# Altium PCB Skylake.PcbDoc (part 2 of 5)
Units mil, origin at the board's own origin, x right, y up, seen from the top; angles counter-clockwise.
Board outline 4000 x 4000 mil, 8 copper layers (TOP LAYER, GND1#2, SIG1#3, SIG2#4, GND2#5, SIG3#6, GND3#7, BOTTOM LAYER), stack 132.6 mil thick; 343 components, 142 nets, 972 pads, 752 vias.
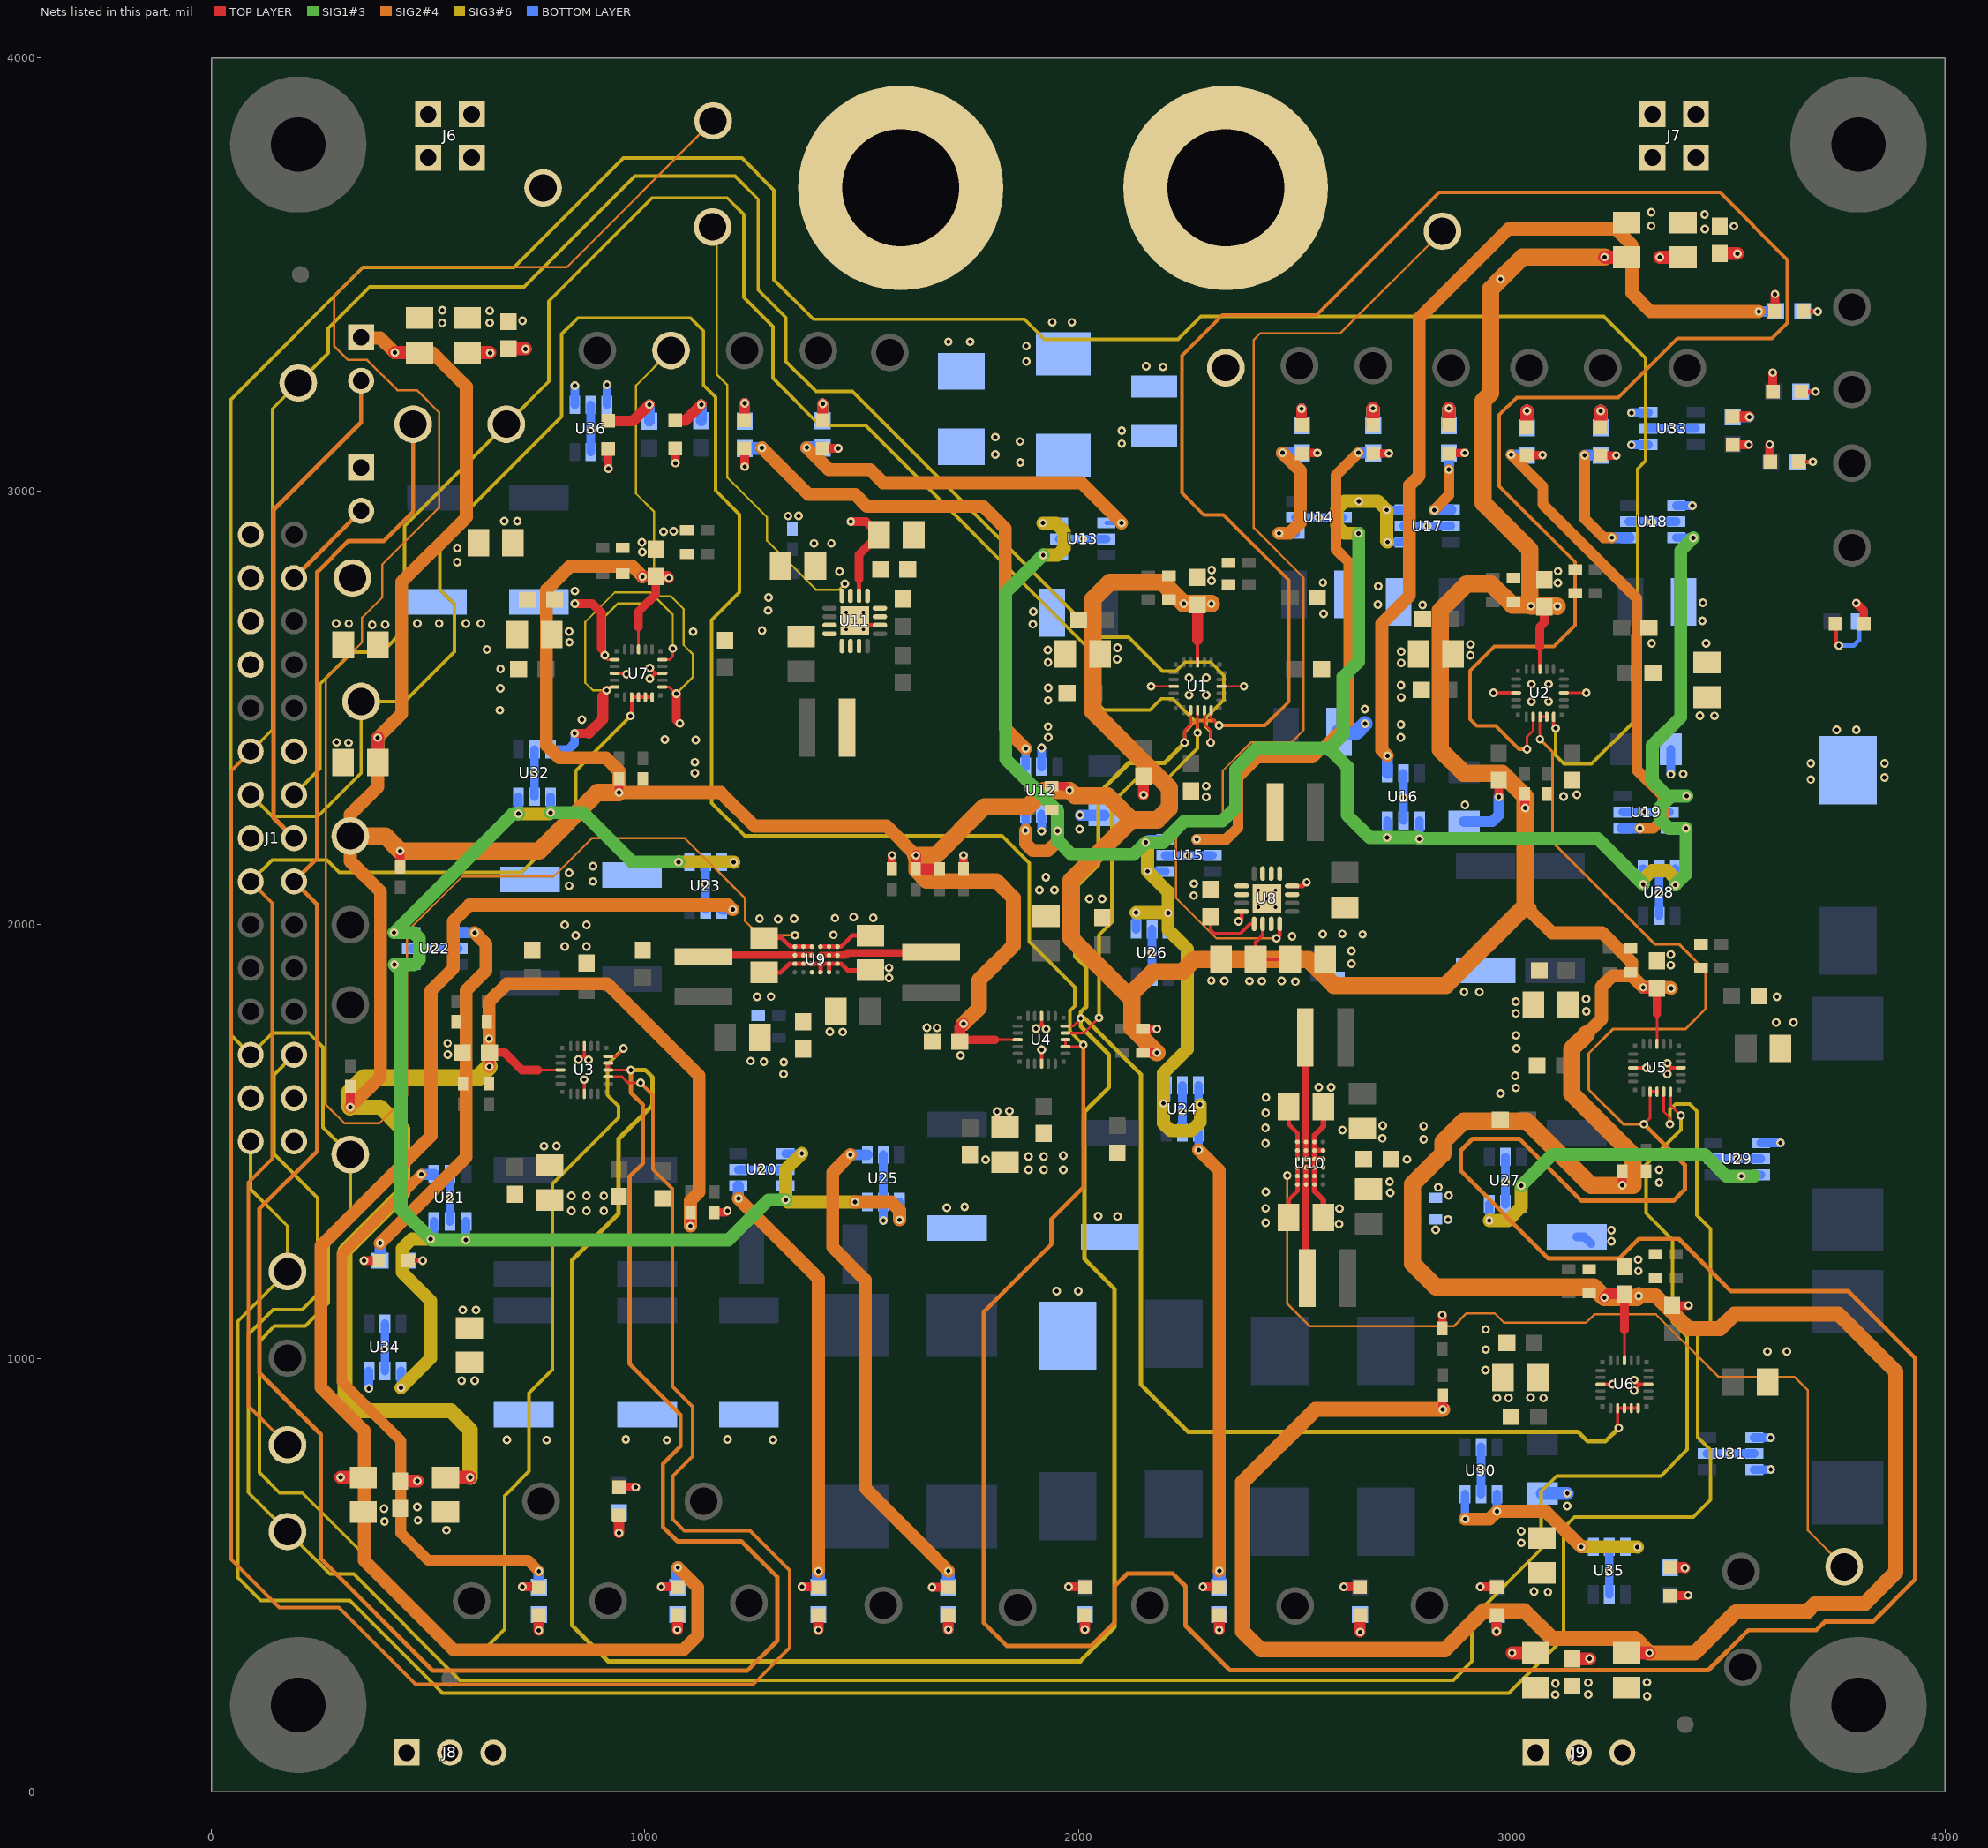
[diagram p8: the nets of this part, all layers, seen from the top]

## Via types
v1: diameter 20, hole 10, TOP LAYER to BOTTOM LAYER, 742 vias
v2: diameter 19.68, hole 7.87, TOP LAYER to BOTTOM LAYER, 10 vias

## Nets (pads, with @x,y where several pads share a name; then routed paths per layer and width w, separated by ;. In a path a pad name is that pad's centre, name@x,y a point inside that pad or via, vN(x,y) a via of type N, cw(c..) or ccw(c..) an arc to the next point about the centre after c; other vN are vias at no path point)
+3.3V_USB: +3.3V_USB.1 C15.1 C16.1 C17.1 C18.1 C20.1 C26.1 C36.1 C52.1 C62.1 C78.1 C88.1 C102.1 J14.1 R1.2 R2.2 R29.2 R30.2 R31.2 R39.2 R40.2 R41.2 R50.2 R51.2 R52.2 R62.2 R63.2 R64.2 R75.2 R76.2 R77.2 R87.2 R88.2 R89.2 R99.2 R100.2 R101.2 U1.18 U2.18 U3.18 U4.18 U5.18 U6.18 U7.18 | length 21363.5
  TOP LAYER w6: 752.95,1665 U3.18@804.88,1665 ; U7.18@985,2635.12 985,2687.05 ; 1807.95,1734.68 U4.18@1859.88,1734.68 ; U6.18@3260,995.12 3260,1065 ; U5.18@3335,1725.12 3335,1795
  TOP LAYER w8: 2274.42,2657.63 2275,2657.05 U1.18@2275,2605.12 ; 3064.42,2642.63 3065,2642.05 U2.18@3065,2590.12
  TOP LAYER w20: v1(319.77,1579.52) 320,1579.75 R2.2@320,1626.38 ; R1.2@435,2133.62 435,2170.13 v1(435.1,2170.23) ; v1(640.46,1672.95) 641.5,1673.99 C52.1@641.5,1705 676.16,1705 716.16,1665 752.95,1665 ; v1(940,2305) R99.2@940,2336.38 ; 985,2687.05 985,2722.17 1025,2762.17 C102.1@1025,2803.5 ; v1(1105,1305) R50.2@1105,1336.38 ; C62.1@1726.5,1730 1731.18,1734.68 1807.95,1734.68 ; R29.2@1938.62,2320 1969.73,2320 v1(1979.78,2309.95) ; R62.2@2148.62,1705 2181.03,1705 v1(2181.07,1704.96) ; v1(2840.86,881.68) v1(2840.86,881.68) R87.2@2840.9,913.93 ; R39.2@3030,2301.38 3030,2270.7 v1(3031.03,2269.67) ; 3064.42,2642.63 3064.42,2686.35 3075,2696.93 C36.1@3075,2733.5 ; v1(3255.01,1398.78) R75.2@3255,1431.38 ; 3260,1065 C88.1@3260,1148.5 ; 3335,1795 C78.1@3335,1853.5
  TOP LAYER w25: v1(994.44,2803.06) 994.88,2803.5 C102.1@1025,2803.5 1051.5,2803.5 v1(1055,2800) ; v1(1625,2160) R64.2@1625,2128.62 R63.2@1680,2128.62 ; C62.1@1726.5,1730 1726.5,1763.5 v1(1735,1772) ; 2274.42,2657.63 2275,2658.21 C26.1@2275,2738.5 ; v1(3213.7,1139.66) 3222.54,1148.5 C88.1@3260,1148.5 ; v1@3305.33,1853.5 C78.1@3335,1853.5
  TOP LAYER w30: v1(383.42,2431.72) 383.51,2431.63 C20.1@383.51,2373.96 ; v1(422.89,3319.79) 423.1,3320 C18.1@480,3320 ; C15.1@540,725 v1@596.52,725 ; v1(3214.16,3540.36) 3214.52,3540 C17.1@3265,3540 ; C16.1@3265,320 v1(3317.67,320)
  SIG2#4 w30: v1(319.77,1579.52) 389.5,1649.25 389.5,2076.81 320,2146.31 +3.3V_USB.1@320,2205 320,2254.74 383.42,2318.16 v1(383.42,2431.72) 438.38,2486.68 438.38,2790.85 587.82,2940.29 587.82,3241.5 509.53,3319.79 v1(422.89,3319.79) 389.17,3353.51 346.49,3353.51 J14.1@345,3355 ; v1(640.46,1672.95) 640.23,1673.18 v1(640.23,1737.31) 640.23,1822.7 681.6,1864.07 912.97,1864.07 1124.93,1652.11 1124.93,1383.56 1105,1363.63 v1(1105,1305) ; v1(994.44,2803.06) 969.89,2827.61 827.99,2827.61 772.66,2772.28 772.66,2414.18 801.84,2385 910,2385 940,2355 v1(940,2305) 1175,2305 1252,2228 1557,2228 v1(1625,2160) ; 3037,2037 3092.48,1981.52 3208.52,1981.52 3276.64,1913.4 3276.64,1882.19 ; 3172.33,1747.48 3207.1,1782.25 3207.1,1857.21 3232.08,1882.19 3276.64,1882.19 ; v1(3368.07,1853.31) 3365.84,1855.54 v1(3303.29,1855.54) 3276.64,1882.19
  SIG2#4 w35: v1(1625,2160) 1625,2125 1649,2101 1811,2101 1850,2062 1850,1952 1771,1873 1771,1808 v1(1735,1772) ; v1(2840.86,881.68) 2546.84,881.68 2379.12,713.96 2379.12,369.56 2421.11,327.57 2845.57,327.57 2935.04,417.04 3029.13,417.04 3092.37,353.8 3283.87,353.8 v1(3317.67,320) 3422.18,320 3517.07,414.89 3680.85,414.89 3698.86,432.9 3813.27,432.9 3885.87,505.5 3885.87,969.64 3753.62,1101.89 3514.04,1101.89 3480.63,1068.48 3407.52,1068.48 3332.24,1143.76 v1(3292.99,1143.76)
  SIG2#4 w40: +3.3V_USB.1@320,2205 400.33,2205 v1(435.1,2170.23) 755.75,2170.23 890.52,2305 v1(940,2305) ; v1(1625,2160) 1671.12,2160 1783.35,2272.23 1883.41,2272.23 1921.13,2309.95 v1(1979.78,2309.95) 1991.91,2297.82 2067.18,2297.82 2123,2242 ; 2123.68,1827.89 1983.5,1968.07 1983.5,2102.5 2123,2242 ; v1(2181.07,1704.96) 2123.68,1762.35 2123.68,1842.71 2171.97,1891 2238.82,1891 2267.82,1920 2530,1920 2590,1860 2848.06,1860 3031.03,2042.97 ; v1(2306.73,2740.48) 2306.43,2740.78 v1(2243.04,2740.78) 2194.13,2789.69 2194.13,2790.33 2072.82,2790.33 2033.29,2750.8 2033.29,2492.55 2209.85,2315.99 2209.85,2269.6 2182.25,2242 2123,2242 ; 3037,2037 3031.03,2042.97 ; v1(3105.04,2734.48) 3104.18,2735.34 v1(3044.36,2735.34) v1@3041.85,2737.85 ; 3172.33,1747.48 3138.16,1713.31 3138.16,1610.43 3280.01,1468.58 3280.01,1398.78 3183.04,1398.78 3034.24,1547.58 2889.5,1547.58 2840.81,1498.89 2840.81,1471.53 2770.66,1401.38 2770.66,1218.62 2824.65,1164.63 3188.73,1164.63 v1(3213.7,1139.66) 3288.89,1139.66 v1(3292.99,1143.76) ; v1(3214.16,3540.36) 3024.64,3540.36 v1(2973.93,3489.65) 2951.23,3466.95 2951.23,3226.28 2933.93,3208.98 2933.93,2972.97 3041.85,2865.05 v1@3041.85,2737.85 ; 3031.03,2042.97 v1(3031.03,2269.67) 3031.03,2295.82 2977.19,2349.66 2889.21,2349.66 2834.69,2404.18 2834.69,2724.96 2895.68,2785.95 2953.01,2785.95 3001.11,2737.85 v1@3041.85,2737.85
  SIG3#6 w35: v1(319.77,1579.52) 389.21,1579.52 440.83,1527.9 440.83,1380.83 307.71,1247.71 307.71,916.95 345.69,878.97 552.27,878.97 596.55,834.69 v1(596.55,724.97)
  SIG3#6 w40: v1(319.77,1579.52) 319.77,1615.17 351.86,1647.26 614.77,1647.26 v1(640.46,1672.95)
  other v1: 1728.15,1698.65
+5V_USB: +5V_USB.1 C7.1 C8.1 C9.1 C10.1 C11.1 C12.1 C13.1 C14.1 C19.1 J15.1 U12.4 U12.6 U13.4 U13.6 U14.4 U14.6 U15.4 U15.6 U16.4 U16.6 U17.4 U17.6 U18.4 U18.6 U19.4 U19.6 U20.4 U20.6 U21.4 U21.6 U22.4 U22.6 U23.4 U23.6 U24.4 U24.6 U25.4 U25.6 U26.4 U26.6 U27.4 U27.6 U28.4 U28.6 U29.4 U29.6 U30.4 U30.6 U31.4 U31.6 U32.4 U32.6 U33.4 U33.6 U34.4 U34.6 U35.4 U35.6 U36.4 U36.6 | length 12583.7
  TOP LAYER w30: v1(297.7,725) C7.1@350,725 ; C8.1@435,716.5 474.7,716.5 v1(474.89,716.69) ; C13.1@590,3320 641.91,3320 v1(642.4,3319.51) ; C14.1@685,3328.5 724.47,3328.5 v1(724.55,3328.58) ; v1(3000.8,319.71) 3001.09,320 C9.1@3055,320 ; C10.1@3140,306.5 3179.82,306.5 v1(3179.86,306.46) ; v1@3341.56,3540 C11.1@3395,3540 ; C12.1@3480,3548.5 3520.65,3548.5 v1(3520.71,3548.44)
  SIG1#3 w30: v1(707.86,2256.06) 695.07,2256.06 v1(420.88,1981.87) 465.57,1981.87 479.11,1968.33 479.11,1919.49 467.68,1908.06 v1(421.55,1908.06) 437.09,1892.52 437.09,1343.59 v1(505.67,1275) 507.59,1273.09 v1(587.01,1273.09) 1192.54,1273.09 1284.67,1365.22 v1(1324.67,1365.22) ; v1(782.05,2258.72) 856.6,2258.72 970.63,2144.69 v1(1077.27,2144.69) ; v1(1918.82,2852.96) 1832.29,2766.43 1832.29,2381.75 1951.97,2262.07 v1(1951.97,2216.55) 1951.97,2194.39 1984.26,2162.1 2127.48,2162.1 v1(2155.08,2189.7) 2195.2,2189.7 2244.93,2239.43 2332.24,2239.43 2362.91,2270.1 2362.91,2358.79 2410.85,2406.73 2578.26,2406.73 ; v1(2646.57,2903.1) 2646.57,2607.5 2610.77,2571.7 2610.77,2439.24 2578.26,2406.73 ; v1(3021.76,1397.89) 3093.39,1469.52 3445.54,1469.52 3495.06,1420 v1(3530,1420) 3559.12,1420 3559.44,1420.32 ; v1(3303.26,2093.38) 3198.1,2198.54 v1(2786.87,2198.54) 2784.14,2201.27 v1(2712.5,2201.27) 2672.38,2201.27 2620.52,2253.13 2620.52,2364.47 2578.26,2406.73 ; 3368.52,2297.1 v1(3403.52,2297.1) ; v1(3376.92,2091.82) 3402.15,2117.05 v1(3402.15,2222.89) 3362.7,2222.89 3342.25,2243.34 3342.25,2270.83 3363.53,2292.11 3324.17,2331.48 3324.17,2413.43 3389.9,2479.16 3389.9,2863.73 v1(3418.84,2892.67)
  SIG2#4 w30: v1(1484.92,1360.6) 1567.89,1360.6 1587.25,1341.24 v1(1587.25,1319.18) ; v1(1878.11,2217.63) 1878.11,2187.56 1894.64,2171.03 1930.13,2171.03 1951.97,2192.87 v1(1951.97,2216.55) ; v1(2892.44,629.06) 2948.3,629.06 v1(2965.92,646.68) 3078.39,646.68 v1(3160.31,564.76)
  SIG3#6 w30: v1(436.88,931.65) 505.06,999.83 505.06,1132.56 439.84,1197.78 439.84,1252.58 462.26,1275 v1(505.67,1275) ; v1(707.86,2256.06) 779.39,2256.06 v1(782.05,2258.72) ; v1(1077.27,2144.69) 1204.51,2144.69 v1(1205.06,2144.14) ; v1(1362.03,1472.3) 1324.67,1434.94 v1(1324.67,1365.22) 1329.29,1360.6 v1(1484.92,1360.6) ; v1(1917.91,2926.79) 1947.8,2926.79 1967.12,2907.47 1967.12,2868.08 1952,2852.96 v1(1918.82,2852.96) ; v1(2133.06,2028.37) 2205.75,2028.37 v1(2207.01,2027.11) ; v1(2155.08,2189.7) 2159.62,2185.16 v1(2159.62,2123.34) 2207.01,2075.95 v1(2207.01,2027.11) ; v1(2281,1585) 2281,1544.66 2261.02,1524.68 2212.98,1524.68 2196,1541.66 v1(2196,1588) 2196,1657.55 2251.28,1712.83 2251.28,1944.24 2207.01,1988.51 v1(2207.01,2027.11) ; v1(2646.57,2903.1) 2613.62,2903.1 2596.25,2920.47 2596.25,2959.52 2613.8,2977.07 v1(2647.07,2977.07) 2691.17,2977.07 v1(2711.12,2957.12) 2711.12,2885.4 v1(2713.56,2882.96) ; v1(2948.08,1317.64) 2991.12,1317.64 3021.76,1348.28 v1(3021.76,1397.89) ; v1(3160.31,564.76) 3289.45,564.76 v1(3289.95,564.26) ; v1(3303.26,2093.38) 3303.26,2105.06 3323.35,2125.15 3359.11,2125.15 3376.92,2107.34 v1(3376.92,2091.82)
  BOTTOM LAYER w20: v1(362.97,930.21) U34.6@363,970.5 ; v1(420.88,1981.87) 421.01,1982 U22.6@460.5,1982 ; v1(421.55,1908.06) 421.61,1908 U22.4@460.5,1908 ; v1(436.88,931.65) 437,931.77 U34.4@437,970.5 ; v1(505.67,1275) 513,1282.32 U21.6@513,1315.5 ; v1(587.01,1273.09) U21.4@587,1315.5 ; v1(707.86,2256.06) 708,2256.2 U32.6@708,2295.5 ; U32.4@782,2295.5 782,2258.77 v1(782.05,2258.72) ; U36.4@838,3199.5 v1(838.01,3243.71) ; U36.6@912,3199.5 912,3245.64 v1(912.13,3245.77) ; v1(1077.27,2144.69) 1077.46,2144.5 U23.4@1103,2144.5 ; U23.6@1177,2144.5 1204.7,2144.5 v1(1205.06,2144.14) ; U20.6@1324.5,1398 1324.5,1365.39 v1(1324.67,1365.22) ; U20.4@1324.5,1472 1361.73,1472 v1(1362.03,1472.3) ; v1(1484.92,1360.6) 1485.02,1360.5 U25.6@1513,1360.5 ; U25.4@1587,1360.5 1587,1319.43 v1(1587.25,1319.18) ; U12.6@1878,2255.5 1878,2217.74 v1(1878.11,2217.63) ; v1(1917.91,2926.79) 1918.12,2927 U13.6@1955.5,2927 ; v1(1918.82,2852.96) 1918.86,2853 U13.4@1955.5,2853 ; v1(1951.97,2216.55) U12.4@1952,2255.5 ; U26.4@2133,1989.5 2133,2028.31 v1(2133.06,2028.37) ; v1(2155.08,2189.7) 2162.38,2197 U15.6@2200.5,2197 ; v1(2159.62,2123.34) 2159.96,2123 U15.4@2200.5,2123 ; v1(2196,1588) 2203,1595 U24.4@2203,1629.5 ; U26.6@2207,1989.5 v1(2207.01,2027.11) ; U24.6@2277,1629.5 2277,1589 v1(2281,1585) ; U14.6@2609.5,2903 2646.47,2903 v1(2646.57,2903.1) ; U14.4@2609.5,2977 2647,2977 v1(2647.07,2977.07) ; v1(2711.12,2957.12) 2711.24,2957 U17.6@2750.5,2957 ; v1(2712.5,2201.27) 2713,2201.77 U16.6@2713,2240.5 ; v1(2713.56,2882.96) v1(2713.56,2882.96) U17.4@2750.5,2883 ; v1(2786.87,2198.54) 2787,2198.67 U16.4@2787,2240.5 ; U30.6@2892,686.19 2892,629.5 v1(2892.44,629.06) ; U27.6@2948,1355.5 2948,1317.72 v1(2948.08,1317.64) ; v1(2965.92,646.68) 2966,646.76 U30.4@2966,686.19 ; v1(3021.76,1397.89) 3022,1397.65 U27.4@3022,1355.5 ; v1(3160.31,564.76) 3160.57,564.5 U35.4@3188,564.5 ; U35.6@3262,564.5 3289.71,564.5 v1(3289.95,564.26) ; v1(3276,3107) 3276,3107.37 3314.87,3107.37 U33.4@3315.5,3108 ; v1(3276,3181) 3276,3181.44 3314.94,3181.44 U33.6@3315.5,3182 ; U28.4@3303,2129.5 3303,2093.64 v1(3303.26,2093.38) ; U19.6@3364.5,2223 3402.04,2223 v1(3402.15,2222.89) ; U19.4@3364.5,2297 3403.42,2297 v1(3403.52,2297.1) ; v1(3376.92,2091.82) 3377,2091.9 U28.6@3377,2129.5 ; U18.6@3379.5,2893 3418.51,2893 v1(3418.84,2892.67) ; U18.4@3379.5,2967 3416.26,2967 v1(3416.64,2966.62) ; v1(3530,1420) 3559.56,1420 3562.56,1423 U29.6@3574.5,1423 ; U31.6@3559.5,743 3597.34,743 v1(3597.54,743.2) ; U31.4@3559.5,817 v1@3597.04,817 ; U29.4@3574.5,1497 v1(3620,1497)
  other v1: 3597.07,817.03 287.72,2695.07 316.58,2694.7 3341.53,3540.03
BATT+: BATT+.1 C1.1 C2.1 C3.1 C4.1 C5.1 C6.1 C21.1 C22.1 C31.2 C41.2 C46.1 C47.1 C57.2 C67.2 C72.1 C73.1 C83.2 C93.2 C97.1 C98.1 C107.2 D1.1 J4.1 R107.1 R109.2 R111.2 R113.2 U1.3 U2.3 U3.3 U4.3 U5.3 U6.3 U7.3 U8.10 U8.11 U8.12 U8_PVIN.1 U9.A1 U9.B1 U9.C1 U9.D1 U9.E1 U9.F1 U9_VIN.1 U10.A1 U10.B1 U10.C1 U10.D1 U10.E1 U10.F1 U10_VIN.1 U11.10 U11.11 U11.12 U11_PVIN.1 | length 11508.9
  TOP LAYER w6: v1@2167.37,2549.42 v1(2167.95,2550) U1.3@2219.88,2550
  TOP LAYER w8: v1(859.53,1642.95) 860,1642.48 U3.3@860,1609.88 ; U7.3@929.88,2580 955.93,2580 v1(957.69,2578.24) ; U4.3@1915,1679.57 1915,1711.37 v1(1915.21,1711.58) ; U8.10@2425.16,2001.93 2425.16,1976.16 2409,1960 C22.1@2409,1920 C21.1@2489,1920 ; v1@2957.37,2534.42 v1(2957.95,2535) U2.3@3009.88,2535 ; U6.3@3204.88,940 3232.61,940 v1(3232.82,940.21) ; U5.3@3279.88,1670 v1@3310.73,1670
  TOP LAYER w10: C47.1@1275,1970 1315.32,1970 1335.79,1949.53 U9.F1@1345.78,1949.53 U9.E1@1365.47,1949.53 U9.D1@1385.15,1949.53 ; U9.C1@1404.84,1949.53 U9.B1@1424.52,1949.53 U9.A1@1444.21,1949.53 1452.4,1949.53 1477.87,1975 C46.1@1520,1975 ; U11.10@1493.84,2759.07 1493.84,2798.14 ; v1(2456.88,1968.75) 2464.53,1976.4 U8.12@2464.53,2001.93 ; C73.1@2485,1325 2485,1365 2505.32,1385.32 U10.F1@2505.32,1400.63 U10.E1@2505.32,1420.31 U10.D1@2505.32,1440 ; C72.1@2485,1580 2485,1540 2505.32,1519.68 U10.A1@2505.32,1499.06 U10.B1@2505.32,1479.37 U10.C1@2505.32,1459.68
  TOP LAYER w20: v1(1475,2930) 1510,2930 C98.1@1540,2900 1493.84,2853.84 1493.84,2798.14
  SIG2#4 w5: U9_VIN.1@1157.17,3854.68 819.3,3516.81 348.1,3516.81 282.99,3451.7 282.99,3334.59 314.65,3302.93 358.97,3302.93 428.61,3233.29 473.58,3233.29 525.15,3181.72 525.15,2962.64 393.78,2831.27 393.78,2755.3 347,2708.52 347,2651.54 263.11,2567.65 263.11,1585.53 306.5,1542.14 387.15,1542.14 450.87,1605.86 450.87,1984.13 578.03,2111.29 789.26,2111.29 877.78,2199.81 1092.04,2199.81 1230.85,2061 1230.85,2008.45 1263.46,1975.84 v1(1346.32,1975.84) ; v1(2456.88,1968.75) 2318.65,1968.75 2225.22,2062.18 2225.22,2205.1 2258.35,2238.23 2313.08,2238.23 2333.14,2258.29 2333.14,2355.64 2397.88,2420.38 2491.23,2420.38 2519.55,2448.7 2519.55,2800.86 2404.57,2915.84 2404.57,3349.57 2419.59,3364.59 2604.59,3364.59 U8_PVIN.1@2840,3600 ; v1(2481.9,1421.68) 2481.9,1125.58 2533.84,1073.64 2865.78,1073.64 2895.91,1103.77 2960.13,1103.77 2981.82,1082.08 3171.51,1082.08 3190.5,1101.07 3332.93,1101.07 3477.58,956.42 3652.84,956.42 3683.43,925.83 3683.43,602.45 U10_VIN.1@3767.07,518.81
  SIG3#6 w5: U11_PVIN.1@1155.83,3609.95 1165.13,3600.65 1165.13,3270.17 1190.3,3245 1190.3,3031.42 1281.72,2940 1281.72,2885.89 1394.44,2773.17 1447.69,2773.17 v1(1461.4,2786.88)
  BOTTOM LAYER w20: v1@1915,1711.37 v1(1915.21,1711.58)
  other v1: 3021.82,574 3021.81,601.01 3073.26,908.03 3043.26,909.53 579.6,1111.41 609.89,1111.41 2432.05,1312.78 2432.05,1345.82 2854.42,1375.56 2432.34,1383.75 2830.4,1394.39 766.77,1489.31 795.81,1489.83 2431.76,1496.09 2431.77,1531.15 2432.05,1565.91 1812.48,1569.02 1840.71,1569.87 2432.85,1601.95 3310.75,1670.02 1274.36,1684.34 1243.73,1685.66 3171.98,1799.99 3171.55,1828.92 2500.44,1868.79 2395,1870 2423,1870 2469.16,1870.5 2493.14,1973.13 1434.8,1976.71 1307.28,2013.06 1264.39,2014.07 1343.96,2013.72 1438.46,2015.37 1526.75,2016.15 1481.56,2017.72 3467.52,2481.87 3434.26,2482.58 2089.51,2612.45 2904.42,2621.89 2090.08,2638.97 2904.81,2646.62 825.62,2651.83 825.19,2676.68 1449,2815 1390,2880 1430,2880 675.29,2930.93 705.29,2930.93 2195.36,3286.98 2156.34,3288.86 1880,3300 1880,3335 1700,3345 1750,3345 1940,3390 1985,3390
GND: C1.2 C2.2 C3.2 C4.2 C5.2 C6.2 C7.2 C8.2 C9.2 C10.2 C11.2 C12.2 C13.2 C14.2 C15.2 C16.2 C17.2 C18.2 C19.2 C20.2 C21.2 C22.2 C23.2 C24.2 C26.2 C27.2 C30.2 C31.1 C32.1 C33.1 C34.1 C35.1 C36.2 C37.2 C40.2 C41.1 C42.1 C43.1 C44.1 C45.1 C46.2 C47.2 C48.1 C49.2 C50.2 C52.2 C53.2 C56.2 C57.1 C58.1 C59.1 C60.1 C61.1 C62.2 C63.2 C66.2 C67.1 C68.1 C69.1 C70.1 C72.2 C73.2 C74.1 C75.2 C76.2 C78.2 C79.2 C82.2 C83.1 C84.1 C85.1 C86.1 C88.2 C89.2 C92.2 C93.1 C94.1 C95.1 C97.2 C98.2 C99.2 C100.2 C102.2 C103.2 C106.2 C107.1 C108.1 D1.2 D2.2 D3.2 D4.2 D5.2 D6.2 D7.2 D8.2 D9.2 D10.2 D11.2 D12.2 D13.2 D14.2 D15.2 D16.2 D17.2 D18.2 D19.2 D20.2 D21.2 D22.2 D23.2 D24.2 D25.2 D26.2 GND.1 J1.3 J1.5 J1.7 J1.15 J1.27 J1.28 J5.1 J6.1 J6.2 J6.3 J6.4 J7.1 J7.2 J7.3 J7.4 J8.1 J8.2 J8.3 J9.1 J9.2 J9.3 R32.1 R33.1 R34.1 R35.2 R36.2 R37.2 R38.2 R42.1 R43.1 R44.1 R45.2 R46.2 R47.2 R48.2 R53.1 R54.1 R55.1 R57.2 R59.2 R60.2 R61.2 R65.1 R66.1 R67.1 R68.2 R69.2 R73.2 R78.1 R79.1 R80.1 R81.2 R83.2 R86.2 R90.1 R91.1 R92.1 R93.2 R97.2 R102.1 R103.1 R104.1 R106.2 R108.1 R110.1 R112.1 R114.1 R116.1 U1.13 U2.13 U3.13 U4.13 U5.13 U6.13 U7.13 U8.5 U8.6 U8.8 U8.15 U8.16 U8.17 U9.A3 U9.B3 U9.B4 U9.C3 U9.C4 U9.D3 U9.E3 U9.F3 U10.A3 U10.B3 U10.B4 U10.C3 U10.C4 U10.D3 U10.E3 U10.F3 U11.6 U11.7 U11.8 U11.15 U11.16 U11.17 U12.2 U12.5 U13.2 U13.5 U14.2 U14.5 U15.2 U15.5 U16.2 U16.5 U17.2 U17.5 U18.2 U18.5 U19.2 U19.5 U20.2 U20.5 U21.2 U21.5 U22.2 U22.5 U23.2 U23.5 U24.2 U24.5 U25.2 U25.5 U26.2 U26.5 U27.2 U27.5 U28.2 U28.5 U29.2 U29.5 U30.2 U30.5 U31.2 U31.5 U32.2 U32.5 U33.2 U33.5 U34.2 U34.5 U35.2 U35.5 U36.2 U36.5 | length 5508.3
  TOP LAYER w6: U1.13@2330.12,2550 v1(2382.05,2550) v1@2382.63,2550.58 ; U2.13@3120.12,2535 v1(3172.05,2535) v1@3172.63,2535.58
  TOP LAYER w8: v1(846.3,1689.04) 850.56,1689.04 860,1698.48 ; U3.13@860,1720.12 860,1698.48 ; v1(870.01,1688.47) 860,1698.48 ; v1(1011.28,2567.88) 1011.79,2567.88 1023.91,2580 ; v1(1011.28,2592.63) 1023.91,2580 ; U7.13@1040.12,2580 1023.91,2580 ; v1(1902.16,1760.47) 1905.21,1760.47 1915,1770.27 ; U4.13@1915,1789.8 1915,1770.27 ; v1(1925.52,1759.74) 1915,1770.27 ; v1(3282.29,925.38) 3296.91,940 ; v1(3282.29,949.69) 3291.98,940 3296.91,940 ; U6.13@3315.12,940 3296.91,940 ; v1(3358.61,1680.55) 3369.16,1670 ; v1(3358.89,1655.89) 3358.89,1659.72 3369.16,1670 ; U5.13@3390.12,1670 3369.16,1670
  TOP LAYER w10: C47.2@1275,1890 1313.15,1890 1333.31,1910.16 U9.F3@1345.78,1910.16 U9.E3@1365.47,1910.16 U9.D3@1385.15,1910.16 U9.C3@1404.84,1910.16 ; U9.C4@1404.84,1890.47 U9.C3@1404.84,1910.16 ; U9.B4@1424.52,1890.47 U9.B3@1424.52,1910.16 ; v2(1484,2701) 1493.84,2691.16 U11.6@1542.07,2691.16 ; C46.2@1520,1895 1467.68,1895 1452.52,1910.16 U9.A3@1444.21,1910.16 U9.B3@1424.52,1910.16 ; v1(2369.49,2007.65) 2376.93,2015.09 U8.8@2376.93,2030.47 ; U8.16@2493.07,2089.53 2517.98,2089.53 v1(2526.58,2098.13) ; U9.C3@1404.84,1910.16 U9.B3@1424.52,1910.16
  TOP LAYER w13: U10.C4@2564.37,1459.68 U10.C3@2544.69,1459.68 ; U10.B4@2564.37,1479.37 U10.B3@2544.69,1479.37 ; C73.2@2565,1325 2565,1365 2544.69,1385.31 U10.F3@2544.69,1400.63 U10.E3@2544.69,1420.31 U10.D3@2544.69,1440 U10.C3@2544.69,1459.68 ; C72.2@2565,1580 2565,1535 2544.69,1514.69 U10.A3@2544.69,1499.06 U10.B3@2544.69,1479.37 ; U10.C3@2544.69,1459.68 U10.B3@2544.69,1479.37
  TOP LAYER w20: v1(351.38,1225.02) D11.2@387.52,1225 ; v1(717.18,472.62) 717.32,472.48 D10.2@755,472.48 ; D25.2@915,3097.52 915,3052.83 v1(915.23,3052.6) ; D23.2@940,702.48 978.61,702.48 v1(978.73,702.36) ; v1(1037.18,472.62) 1037.32,472.48 D12.2@1075,472.48 ; v1(1070,3065) D21.2@1070,3099.02 ; R53.1@1160,1336.38 1186.38,1336.38 v1(1190,1340) ; v1(1230,3057) D26.2@1230,3099.02 ; v1(1362.18,472.62) 1362.32,472.48 D9.2@1400,472.48 ; D2.2@1410,3099.02 v1@1446.23,3099.02 ; R67.1@1570,2128.62 v1(1570,2160) ; v1(1662.18,471.64) 1662.32,471.5 D14.2@1700,471.5 ; R66.1@1735,2128.62 v1(1735,2160) ; v1(1977.18,472.62) 1977.32,472.48 D15.2@2015,472.48 ; R65.1@2148.62,1760 2180.94,1760 v1(2181.06,1759.88) ; v1(2287.18,472.62) 2287.32,472.48 D13.2@2325,472.48 ; D3.2@2515,3088.5 v1@2551.23,3088.5 ; v1(2612.18,472.62) 2612.32,472.48 D19.2@2650,472.48 ; D4.2@2680,3087.52 v1@2716.23,3087.52 ; v1(2839.93,1099.76) 2840,1099.69 R90.1@2840,1068.62 ; D6.2@2855,3088.5 v1@2891.23,3088.5 ; v1(2927.18,472.62) 2927.32,472.48 D20.2@2965,472.48 ; C42.1@2970,2333.5 2970,2295.44 v1(2970.26,2295.18) ; D8.2@3035,3083.5 v1@3071.23,3083.5 ; D7.2@3205,3082.52 v1@3241.23,3082.52 ; D24.2@3365,452.52 3398.64,452.52 3399.12,453 v1(3407,453) ; C95.1@3370,1121.5 3407.8,1121.5 v1(3407.96,1121.66) ; D22.2@3510,3107.52 3546.51,3107.52 v1(3546.77,3107.78) ; D16.2@3595.31,3068.13 v1(3595.32,3108) ; D17.2@3602.26,3234.05 v1(3602.27,3273.92) ; D5.2@3607.52,3415 v1(3607.53,3454.87) ; v1(3794.87,2742.47) 3812.48,2724.86 D18.2@3812.48,2695
  TOP LAYER w25: C32.1@2150,2343.5 2150,2299.59 v1(2150.13,2299.46)
  BOTTOM LAYER w20: U34.5@400,970.5 U34.2@400,1079.5 ; U22.5@460.5,1945 U22.2@569.5,1945 ; U21.5@550,1315.5 U21.2@550,1424.5 ; U32.5@745,2295.5 U32.2@745,2404.5 ; U36.2@875,3090.5 U36.5@875,3199.5 ; U23.2@1140,2035.5 1140,2093.79 v1(1139.92,2093.87) 1140,2093.95 U23.5@1140,2144.5 ; U20.2@1215.5,1435 U20.5@1324.5,1435 ; U25.2@1550,1469.5 U25.5@1550,1360.5 1550,1317.66 v1(1550.31,1317.35) ; U12.5@1915,2255.5 1915,2216.13 v1(1915.13,2216) ; U12.2@1915,2364.5 1915,2407.97 v1(1915.07,2408.04) ; U13.5@1955.5,2890 v1(2010.29,2890) U13.2@2064.5,2890 ; U26.2@2170,1880.5 U26.5@2170,1989.5 ; U15.5@2200.5,2160 U15.2@2309.5,2160 ; U24.2@2240,1520.5 U24.5@2240,1629.5 ; U14.2@2500.5,2940 U14.5@2609.5,2940 ; U16.5@2750,2240.5 U16.2@2750,2349.5 ; U17.5@2750.5,2920 U17.2@2859.5,2920 ; v1@2852.93,1320 v1(2853.03,1320.1) ; U30.5@2929,686.19 U30.2@2929,795.19 ; v1(2984.89,1406.25) 2985,1406.36 U27.2@2985,1464.5 ; U27.5@2985,1355.5 v1@2985,1406.02 ; v1@3119.46,2296.38 v1(3119.63,2296.21) ; R81.2@3150,1279.92 3167.6,1279.92 R81.2@3182.62,1264.9 ; U35.2@3225,455.5 3225,508.83 v1(3224.9,508.93) 3225,509.03 U35.5@3225,564.5 ; U19.2@3255.5,2260 U19.5@3364.5,2260 ; U18.2@3270.5,2930 U18.5@3379.5,2930 ; U33.5@3315.5,3145 U33.2@3424.5,3145 ; U28.2@3340,2020.5 3340,2073.18 v1(3339.87,2073.31) 3340,2073.44 U28.5@3340,2129.5 ; R48.2@3367.09,2405 3367.09,2347.31 v1(3367.17,2347.23) ; U31.2@3450.5,780 U31.5@3559.5,780 ; U29.2@3465.5,1460 U29.5@3574.5,1460
  BOTTOM LAYER w25: v1(2004.03,2252.99) 2004.11,2252.91 R35.2@2060,2252.91 ; R45.2@2890,2237.91 2955.16,2237.91 2970.26,2253.01 v1(2970.26,2295.18)
  BOTTOM LAYER w30: R93.2@3070,687.91 3128,687.91 v1(3128.25,688.16)
  BOTTOM LAYER w35: R38.2@2601.02,2445 2642.52,2445 v1(2661.35,2463.83)
  other v1: 3312.35,220.33 3100.25,223.73 3176.55,224.41 3100.78,249.51 3176.55,251.43 3311.68,252.24 3083.37,460.48 3051.13,461.27 542.11,603.41 398.85,623.38 476.17,625.9 397.75,653 474.42,657.12 3128.04,659.29 2929.02,744.43 3503.77,779.92 773.04,811.3 1050.48,811.12 681.48,811.93 1295.19,812.01 955.82,812.86 1190.34,812.86 2965.77,908.66 2992.7,908.66 576.96,947.94 606.98,948.05 2939.69,972.57 3590,1015 3635,1015 2939.81,1019.88 399.81,1021.24 2939.83,1066.58 1950,1155 2000,1155 3292.18,1201.26 3291.59,1227.46 3230,1270 3230,1295 2824.55,1296.22 2601.26,1309.28 2090.53,1327.23 2045.79,1327.72 830,1340 865,1340 905,1340 2602.45,1344.9 1696.31,1347.4 1737.53,1349.21 550.07,1369.65 830,1375 865,1375 905,1375 2719.16,1381.59 3340,1405 2717.95,1407.5 1268.69,1434.99 1885,1435 1920,1435 1965,1435 3340,1435 1785.98,1458.39 2758.46,1458.81 3520,1460 1885,1465 1920,1465 1965.06,1467.24 2796.47,1505.12 2701.46,1507.37 2609.14,1526.51 2796.47,1535.33 2702.09,1536.45 2239.99,1568.66 2974.23,1610.56 3009.24,1623.51 2554.73,1625.34 2582.98,1625.1 3007.99,1651.45 1319.83,1655.42 1320.29,1683.46 545.3,1700.32 3010.81,1714.86 544.59,1726.38 3009.87,1744.7 1426.6,1753.41 1455.8,1752.71 1674.2,1762.15 1650.71,1762.55 3610,1775 3650,1775 3009.27,1795.48 3009.23,1822.61 1258.52,1833.68 1290.86,1834.15 3611.7,1833.92 2890,1845 2925,1845 2336.91,1870.14 2306.75,1871.09 1562.91,1877.62 1563.07,1900.58 3367.08,1906.72 2630,1910 3367.08,1931.73 2170.06,1934.93 2630,1940 513.74,1944.61 815,1950 865,1950 840,1975 2563.71,1978.35 2655.76,1977.87 2609.02,1979 815,2000 865,2000 2025.3,2059.9 2055,2059.9 2265.99,2067.36 1910,2080 1945,2080 825,2090 2266.47,2094.91 880,2100 1925,2110 825,2120 880,2135 2253.14,2159.82 2002.83,2220.33 3307.09,2259.98 2891.9,2276.37 2749.97,2293.6 2295,2295 3150,2300 2295,2320 3690,2335 3860,2340 3395.31,2347.97 1115,2350 745.13,2350.7 3690,2372.6 3860,2372.6 1115,2375 316.12,2419.59 288.62,2420.73 1930.25,2432.19 2743.68,2432.53 3750,2450 3795,2450 1929.92,2457.24 2744.3,2462.04 665,2495 2660.93,2497.86 3045,2515 3085,2515 1929.92,2517.46 2745,2524.67 2255,2530 2295,2530 665.98,2545.25 1930.78,2546.57 2744.3,2552.77 3045,2555 3085,2555 2255,2570 2295,2570 666.65,2590.36 2744.96,2604.11 1929.92,2605.64 2744.96,2630.23 1929.63,2634.18 635.19,2635.18 3448.56,2649.19 3322.78,2649.5 1270.23,2678.86 370.52,2692.09 400.33,2692.67 1894.81,2693.42 475,2695 525,2695 586.9,2694.88 621.19,2694.88 3439.75,2701.1 2565.85,2717.16 1896.06,2722.3 1284,2725 2794.18,2737.91 2690.81,2738.86 3440.89,2743.12 1285.17,2755.04 2692.07,2781 2564.07,2789.38 3106.5,2788.91 2307.46,2793.51 3106.73,2815.6 2307.53,2817.94 566.78,2836.44 993.64,2860.21 566.91,2868.94 993.05,2882.33 1042.57,2906.61 1066.54,2907.67 2805.28,2919.91 3323.91,2928.85 2553.91,2939.66 1330.24,2943.1 1354.04,2943.52 1865.84,3066.69 3241.26,3082.55 3071.26,3083.53 1808.5,3085 2716.26,3087.55 2551.26,3088.53 2891.26,3088.53 1446.26,3099.05 2100,3110 1865,3115 1808.5,3125 2100,3140 875.2,3141.05 3369.33,3144.34 532.08,3388.66 641.84,3388.89 717.43,3393.23 641.84,3416.48 532.29,3417.83 3445.53,3605.38 3321.8,3611.99 3512.4,3611.77 3444.89,3638.94 3321.8,3643.86
  other v2: 2415.32,2040.31 2454.69,2040.32 2435,2060 2415.31,2079.68 2454.68,2079.69 1464.32,2681.31 1503.69,2681.32 1464.31,2720.69 1503.68,2720.69
GPIO2: GPIO2.1 J1.17 U7.7 U7.8 U7.9 U7.10 | length 2594.5
  TOP LAYER w8: v1(966.47,2481.6) 969.25,2484.38 U7.7@969.25,2524.88 U7.8@985,2524.88 U7.9@1000.75,2524.88 U7.10@1016.5,2524.88
  SIG2#4 w8: J1.17@90,2100 139.86,2050.14 139.86,1460 85,1405.14 85,890 GPIO2.1@175,800
  SIG3#6 w8: J1.17@90,2100 139.55,2149.55 265.81,2149.55 294.45,2120.91 714.91,2120.91 840.08,2246.08 840.08,2355.21 v1(966.47,2481.6)
GPIO3: GPIO3.1 J1.18 U1.7 U1.10 U2.7 U3.8 U3.9 U4.10 U6.7 U6.8 U6.9 U6.10 | length 18066
  TOP LAYER w6: U3.8@915.12,1665 v1(967.05,1665) v1@967.63,1665.58 ; U4.10@1970.12,1766.18 1988.71,1766.18 2005.26,1782.74 v1(2005.26,1784.3) ; v1(2245,2420) 2245,2448.41 2259.25,2462.66 U1.7@2259.25,2494.88 ; U1.10@2306.5,2494.88 2306.5,2476.29 2324.62,2458.17 v1(2324.62,2459.74) ; v1(3035,2405) 3035,2433.41 3049.25,2447.66 U2.7@3049.25,2479.88
  TOP LAYER w8: U3.8@915.12,1665 U3.9@915.12,1680.75 ; v1(3247.08,839.26) 3244.25,842.09 U6.7@3244.25,884.88 U6.8@3260,884.88 U6.9@3275.75,884.88 U6.10@3291.5,884.88
  SIG2#4 w8: v1(2245,2420) 2245,2444.91 2270.74,2470.65 2313.71,2470.65 v1(2324.62,2459.74) 2430.25,2459.74 2485.77,2515.26 2485.77,2794.54 2334.49,2945.82 2289.4,2945.82 2238.78,2996.44 2238.78,3312.77 2332.33,3406.32 2549.07,3406.32 2832.19,3689.44 3480.56,3689.44 3635.96,3534.04 3635.96,3388.22 3600.25,3352.51 3381.85,3352.51 3245.93,3216.59 3011.41,3216.59 2971.16,3176.34 2971.16,3011.48 3145.61,2837.03 3145.61,2691.08 3096.74,2642.21 2959.91,2642.21 2904,2586.3 2904,2474 2919,2459 2962.4,2459 3016.4,2405 v1(3035,2405)
  SIG2#4 w10: GPIO3.1@465,3155 465,2953.05 397.54,2885.59 315.59,2885.59 244.01,2814.01 244.01,2154.01 J1.18@190,2100 244.01,2045.99 244.01,1478.36 110,1344.35 110,966.36 252.36,824 252.36,537.01 510.48,278.89 1235.91,278.89 1305.6,348.58 1305.6,494.4 1222.53,577.47 1074.78,577.47 1041.27,610.98 1041.27,755.89 1082.04,796.66 1082.04,869.47 964.27,987.24 964.27,1418.86 995.13,1449.72 995.13,1584.71 967.05,1612.79 v1(967.05,1665)
  SIG3#6 w10: v1(967.05,1665) 1000.56,1665 1017.56,1648 1017.56,1584.46 939,1505.9 939,1333.2 831.84,1226.04 831.84,383.65 914.44,301.05 2004.69,301.05 2083.35,379.71 2083.35,1159.61 2013.66,1229.3 2013.66,1568.06 2070.55,1624.95 2070.55,1700.34 2005.26,1765.63 v1(2005.26,1784.3) ; v1(2245,2420) 2198.47,2373.47 2116.9,2373.47 2046.03,2302.6 2046.03,2138.73 1992.22,2084.92 1992.22,1927.22 2018.22,1901.22 2018.22,1811.5 2005.26,1798.54 v1(2005.26,1784.3) ; v1(3247.08,839.26) 3216.02,808.2 3175.05,808.2 3153.63,829.62 2253.55,829.62 2144.08,939.09 2144.08,1654.81 2014.59,1784.3 v1(2005.26,1784.3)
GPIO4: GPIO4.1 J1.13 U2.8 U2.9 U4.7 U4.8 U5.7 U5.8 | length 12536.5
  TOP LAYER w6: U4.8@1970.12,1734.68 U4.7@1970.12,1718.94 2007.24,1718.94 v1(2011.44,1723.14) ; v1@3065.58,2427.37 v1(3065,2427.95) U2.8@3065,2479.88 U2.9@3080.75,2479.88 ; v1(3305,1540) 3319.25,1554.25 U5.7@3319.25,1614.88
  TOP LAYER w8: U5.7@3319.25,1614.88 U5.8@3335,1614.88
  SIG2#4 w6: v1(3065,2427.95) 3093.81,2399.14 3093.81,2191.19 3329.71,1955.29 3385.61,1955.29 3447.53,1893.37 3447.53,1806.2 3400.38,1759.05 3233.05,1759.05 3177.73,1703.73 3177.73,1619.59 3257.32,1540 v1(3305,1540)
  SIG2#4 w10: v1(2011.44,1723.14) 2011.44,1592.02 2011.44,1394.54 1937.9,1321 1937.9,1263.45 1782.28,1107.83 1782.28,388.64 1834.95,335.97 2029.04,335.97 2083.73,390.66 2083.73,474.04 2112.76,503.07 2217.79,503.07 2247.08,473.78 2247.08,383.07 2349.77,280.38 3453.43,280.38 3545.55,372.5 3702.69,372.5 3722.3,392.11 3833.15,392.11 3930.76,489.72 3930.76,1000.66 3776.79,1154.63 3505.96,1154.63 3385.18,1275.41 3293.11,1275.41 3247.62,1229.92 3084.58,1229.92 2882.57,1431.93 2882.57,1479.63 2908.77,1505.83 3018.28,1505.83 3161.02,1363.09 3373.07,1363.09 3399.18,1389.2 3399.18,1445.82 v1(3305,1540)
  SIG3#6 w8: J1.13@90,2300 139.87,2250.13 245.13,2250.13 345,2350 GPIO4.1@345,2515 445,2515 560,2630 560,2740.26 526.92,2773.34 526.92,2891.55 808,3172.63 808,3363 845,3400 1105,3400 1135,3370 1135,3245.14 1162.68,3217.46 1162.68,3002.03 1218,2946.71 1218,2767 1154,2703 1154,2281 1230,2205 1824,2205 1886.81,2142.19 1886.81,1961.03 1991.67,1856.17 1991.67,1812.63 1980.3,1801.26 1980.3,1754.28 v1(2011.44,1723.14)
GPIO5: GPIO5.1 J1.14 U1.8 U4.9 | length 4745.7
  TOP LAYER w6: U4.9@1970.12,1750.43 2012.77,1750.43 v1(2047.71,1785.37) ; v1(2275,2442.95) U1.8@2275,2494.88
  SIG3#6 w8: J1.14@190,2300 250,2360 250,2555 324,2629 393,2629 445.45,2681.45 445.45,2920.45 GPIO5.1@680,3155 778.39,3253.39 778.39,3438.65 1016.62,3676.88 1189.85,3676.88 1228,3638.73 1228,3447 1295,3380 1295,3261 1403.71,3152.29 1508.77,3152.29 2019.4,2641.66 2019.4,2534.92 2058.83,2495.49 2165.12,2495.49 2191.09,2521.46 2217.91,2521.46 2275,2464.37 v1(2275,2442.95) 2275,2406.54 2209.81,2341.35 2137.8,2341.35 2076.86,2280.41 2076.86,2005.81 2047.71,1976.66 v1(2047.71,1785.37)
GPIO6: GPIO6.1 J1.11 U1.9 U3.7 | length 9174.6
  TOP LAYER w6: U3.7@915.12,1649.25 947.34,1649.25 961.59,1635 v1(990,1635) ; U1.9@2290.75,2494.88 2290.75,2462.37 2305,2448.12 v1(2305,2420)
  SIG2#4 w8: J1.11@90,2400 45.33,2355.33 45.33,535.67 156,425 293.84,425 470.91,247.93 1249.99,247.93 1334.21,332.15 1334.21,510.1 1242.38,601.93 1090.94,601.93 1064.11,628.76 1064.11,728.18 1109.65,773.72 1109.65,888.36 1063.16,934.85 1063.16,1391 1018.2,1435.96 1018.2,1606.8 v1(990,1635)
  SIG3#6 w8: J1.11@90,2400 140.28,2450.28 140.28,3190.28 GPIO6.1@200,3250 268.87,3318.87 268.87,3376.13 364.74,3472 721.27,3472 976.99,3727.72 1207.3,3727.72 1261.18,3673.84 1261.18,3464.82 1325,3401 1325,3300 1394.66,3230.34 1478.72,3230.34 2045.38,2663.68 2115.74,2663.68 2194.42,2585 2225,2585 2245.94,2605.94 2304.82,2605.94 2335.62,2575.14 2335.62,2518.61 2294.65,2477.64 2294.65,2455.97 2305,2445.62 v1(2305,2420)
GPIO7: J1.12
GPIO8: GPIO8.1 J1.25 U2.10 U3.10 | length 10158.8
  TOP LAYER w6: U3.10@915.12,1696.5 933.71,1696.5 950.26,1713.05 v1(950.26,1714.62)
  TOP LAYER w8: U2.10@3096.5,2479.88 3096.5,2457.93 v1(3101.18,2453.25)
  SIG3#6 w8: v1(950.26,1714.62) 913.91,1678.27 913.91,1607.02 939.18,1581.75 939.18,1554.63 786.61,1402.06 786.61,973.28 732.72,919.39 732.72,739.11 676.11,682.5 676.11,375.07 632.49,331.45 567.07,331.45 209.52,689 157,689 110,736 110,1039 145,1074 216,1074 269,1127 269,1265.51 320,1316.51 GPIO8.1@320,1470 257.14,1532.86 257.14,1717.63 224.88,1749.89 139.89,1749.89 J1.25@90,1700 44.05,1745.95 44.05,3211.56 348.96,3516.47 697.9,3516.47 950.16,3768.73 1223.87,3768.73 1297.55,3695.05 1297.55,3488.45 1389,3397 1875.45,3397 1921.87,3350.58 2229.78,3350.58 2282.65,3403.45 3212.13,3403.45 3309.1,3306.48 3309.1,3070.44 3290.55,3051.89 3290.55,2679.86 3279.07,2668.39 3279.07,2466.29 3184,2371.22 3120.3,2371.22 3101.18,2390.34 v1(3101.18,2453.25)
GPIO9: GPIO9.1 J1.26 U5.10 | length 5940.6
  TOP LAYER w6: U5.10@3366.5,1614.88 3366.5,1583.5 v1(3390,1560)
  SIG3#6 w8: J1.26@190,1700 143.55,1653.55 143.55,1471.45 245,1370 245,1148 209,1112 142,1112 85,1055 85,690 GPIO9.1@175,600 273,502 328,502 572.82,257.18 2864.78,257.18 2908.03,300.43 2908.03,399.66 3068.05,559.68 3068.05,692.88 3103.74,728.57 3344.16,728.57 3404.83,789.24 3404.83,1049.55 3371.3,1083.08 3371.3,1272.69 3309.59,1334.4 3309.59,1446.98 3390,1527.39 v1(3390,1560)
GPIO10: GPIO10.1 J1.29 U5.9 | length 6055.8
  TOP LAYER w6: U5.9@3350.75,1614.88 3350.75,1569.25 3365,1555 v1(3365,1540)
  SIG3#6 w8: J1.29@90,1500 90,1390 175,1305 GPIO10.1@175,1200 60,1085 60,494 113,441 318.84,441 532.61,227.23 2992.95,227.23 3119.4,353.68 3119.4,608.35 3144.57,633.51 3418.85,633.51 3458.74,673.4 3458.74,788.09 3428.68,818.15 3428.68,1050.52 3458.74,1080.58 3458.74,1298.06 3427,1329.8 3427,1570.48 3410.86,1586.62 3377.82,1586.62 3365,1573.8 v1(3365,1540)
GPIO11: J1.30
GPIO12: J1.1
MODPHY: "ModPHY [1.0V,2.40A].1" C108.2 R105.1 U7.1 U7.5 U7.11 U7.15 U32.3 | length 2273.3
  TOP LAYER w6: v1@899.29,2625.61 899.29,2636.91 ; 902.73,2527 902.73,2539.75 911.48,2548.5 U7.5@929.88,2548.5 ; v1@905.27,2619.64 913.4,2611.5 U7.1@929.88,2611.5 ; U7.11@1040.12,2548.5 1055.55,2548.5 v1@1070.84,2533.21 ; U7.15@1040.12,2611.5 1056.84,2611.5 1064.2,2618.86 v1(1064.2,2637.4)
  TOP LAYER w20: v1(837.66,2441.35) 837.81,2441.5 870,2441.5 ; v1(837.86,2741.17) 878.33,2741.17 899.29,2720.21 899.29,2636.91 ; v1(1072.08,2533.21) 1072.08,2472.25 v1@1080,2464.33
  TOP LAYER w25: 870,2441.5 902.73,2474.23 902.73,2527
  SIG3#6 w5: v1(907.48,2621.85) 907.48,2711.48 937,2741 1003.98,2741 1021.14,2758.16 ; v1(911.17,2540.79) 879.56,2540.79 862.19,2558.16 862.19,2698.72 930.28,2766.81 1012.49,2766.81 1021.14,2758.16 ; 1060,3325 979.11,3244.11 979.11,2994.96 1021.14,2952.93 1021.14,2758.16 ; v1(1064.2,2637.4) 1064.2,2715.1 1021.14,2758.16 ; v1(1072.08,2533.21) 1109.95,2571.08 1109.95,2624.82 1089.18,2645.59 1089.18,2728.65 1059.67,2758.16 1021.14,2758.16
  BOTTOM LAYER w20: U32.3@782,2404.5 823.57,2404.5 837.66,2418.59 v1(837.66,2441.35)
  other v1: 1116.79,2426.11 1045.77,2427.53 1080.28,2464.61 854.75,2473.28 1110.68,2676.22 837.86,2769.98
NetC23_1: C23.1 U8.9 | length 143.9
  TOP LAYER w8: C23.1@2305,2018.5 2305,1987.58 2312.97,1979.61 2373.61,1979.61 2395.93,2001.93 U8.9@2405.47,2001.93
NetC48_2: C48.2 U9.D4
NetC74_2: C74.2 U10.D4
NetC99_1: C99.1 U11.9
NetD2_1: D2.1 R4.1 | length 76.4
  TOP LAYER w25: D2.1@1410,3163.98 v1@1410,3201.7
  BOTTOM LAYER w25: R4.1@1410,3162.99 v1@1410,3201.7
  other v1: 1410.07,3201.77
NetD3_1: D3.1 R5.1 | length 76.4
  TOP LAYER w25: D3.1@2515,3152.48 v1@2515,3190.21
  BOTTOM LAYER w25: R5.1@2515,3151.5 v1@2515,3190.21
  other v1: 2515.07,3190.28
NetD4_1: D4.1 R6.1 | length 78.4
  TOP LAYER w30: D4.1@2680,3152.48 v1@2680,3191.19
  BOTTOM LAYER w30: R6.1@2680,3151.5 v1@2680,3191.19
  other v1: 2680.07,3191.26
NetD5_1: D5.1 R7.1 | length 68.4
  TOP LAYER w10: D5.1@3672.48,3415 3706.1,3415 v1(3706.16,3415.06)
  BOTTOM LAYER w10: R7.1@3671.5,3415 3706.1,3415 v1(3706.16,3415.06)
NetD6_1: D6.1 R8.1 | length 78.4
  TOP LAYER w30: D6.1@2855,3152.48 v1@2855,3191.19
  BOTTOM LAYER w30: R8.1@2855,3151.5 v1@2855,3191.19
  other v1: 2855.07,3191.26
NetD7_1: D7.1 R9.1 | length 76.4
  TOP LAYER w30: D7.1@3205,3147.48 v1@3205,3185.21
  BOTTOM LAYER w30: R9.1@3205,3146.5 v1@3205,3185.21
  other v1: 3205.07,3185.28
NetD8_1: D8.1 R10.1 | length 76.4
  TOP LAYER w30: D8.1@3035,3147.48 v1@3035,3185.21
  BOTTOM LAYER w30: R10.1@3035,3146.5 v1@3035,3185.21
  other v1: 3035.07,3185.28
NetD9_1: D9.1 R11.1 | length 69.5
  TOP LAYER w25: v1@1400,373.38 D9.1@1400,407.52
  BOTTOM LAYER w10: R11.1@1400,408.5 1400.16,408.34 v1(1400.16,373.22)
NetD10_1: D10.1 R12.1 | length 72.6
  TOP LAYER w25: v1@755,371.74 D10.1@755,407.52
  BOTTOM LAYER w10: R12.1@755,408.5 755,371.74 v1(755.06,371.68)
NetD11_1: D11.1 R13.1 | length 70.6
  TOP LAYER w10: D11.1@452.48,1225 487.22,1225 v1(487.28,1225.06)
  BOTTOM LAYER w10: R13.1@451.5,1225 487.22,1225 v1(487.28,1225.06)
NetD12_1: D12.1 R14.1 | length 69.4
  TOP LAYER w25: v1(1074.66,373.45) 1075,373.79 D12.1@1075,407.52
  BOTTOM LAYER w10: v1(1074.66,373.45) 1075,373.79 R14.1@1075,408.5
NetD13_1: D13.1 R15.1 | length 70.3
  TOP LAYER w25: v1(2324.92,372.87) 2325,372.95 D13.1@2325,407.52
  BOTTOM LAYER w10: v1(2324.92,372.87) 2324.92,408.42 R15.1@2325,408.5
NetD14_1: D14.1 R16.1 | length 68.3
  TOP LAYER w25: v1(1699.91,373.9) 1700,373.99 D14.1@1700,407.52
  BOTTOM LAYER w10: v1(1699.91,373.9) 1700,373.99 R16.1@1700,408.5
NetD15_1: D15.1 R17.1 | length 67.5
  TOP LAYER w25: v1@2015,374.33 D15.1@2015,407.52
  BOTTOM LAYER w10: R17.1@2015,408.5 2015,374.33 v1(2015.12,374.21)
NetD16_1: D16.1 R18.1 | length 68.4
  TOP LAYER w10: D16.1@3661.25,3068.13 3694.87,3068.13 v1(3694.93,3068.19)
  BOTTOM LAYER w10: R18.1@3660.27,3068.13 3694.87,3068.13 v1(3694.93,3068.19)
NetD17_1: D17.1 R19.1 | length 68.4
  TOP LAYER w10: D17.1@3667.48,3230 3701.1,3230 v1(3701.16,3230.06)
  BOTTOM LAYER w10: R19.1@3666.5,3230 3701.1,3230 v1(3701.16,3230.06)
NetD18_1: D18.1 R20.1 | length 152.5
  TOP LAYER w10: D18.1@3755,2695 3747.52,2687.52 3747.52,2651.38 v1(3755.06,2643.84)
  BOTTOM LAYER w10: v1@3755,2643.9 3788.77,2643.9 3801.5,2656.63 R20.1@3801.5,2700
NetD19_1: D19.1 R21.1 | length 79.5
  TOP LAYER w25: v1@2650,368.39 D19.1@2650,407.52
  BOTTOM LAYER w10: R21.1@2650,408.5 2650,368.39 v1(2650.15,368.24)
NetD20_1: D20.1 R22.1 | length 76
  TOP LAYER w25: v1(2964.88,370.06) 2965,370.18 D20.1@2965,407.52
  BOTTOM LAYER w10: v1(2964.88,370.06) 2965,370.18 R22.1@2965,408.5
NetD21_1: D21.1 R23.1 | length 111.9
  TOP LAYER w25: D21.1@1070,3163.98 1093.98,3163.98 v1(1130,3200)
  BOTTOM LAYER w25: R23.1@1130,3162.99 v1(1130,3200)
NetD22_1: D22.1 R24.1 | length 76.4
  TOP LAYER w10: v1@3547.13,3172.48 v1(3548.04,3171.57)
  TOP LAYER w25: D22.1@3510,3172.48 v1@3547.13,3172.48
  BOTTOM LAYER w25: R24.1@3510,3171.5 v1@3547.97,3171.5
NetD23_1: D23.1 R25.1 | length 87.5
  TOP LAYER w25: v1@940,596.78 D23.1@940,637.52
  BOTTOM LAYER w10: R25.1@940,643.5 940,596.78 v1(940.05,596.73)
NetD24_1: D24.1 R26.1 | length 70.3
  TOP LAYER w25: D24.1@3365,517.48 3398.09,517.48 v1(3399.7,515.87)
  BOTTOM LAYER w10: R26.1@3365,516.5 3399.07,516.5 v1(3399.7,515.87)
NetD25_1: D25.1 R27.1 | length 149
  TOP LAYER w25: D25.1@915,3162.48 972.48,3162.48 v1(1010,3200)
  BOTTOM LAYER w25: R27.1@1010,3161.5 v1(1010,3200)
NetD26_1: D26.1 R3.1 | length 80
  TOP LAYER w25: D26.1@1230,3163.98 v1@1230,3202.69
  BOTTOM LAYER w25: R3.1@1230,3161.5 1230,3202.69 v1(1230.07,3202.76)
NetJ1_4: J1.4 J15.2 | length 219.2
  SIG2#4 w10: J1.4@190,2800 J15.2@345,2955
NetJ1_16: J1.16 J14.2 | length 1158.3
  SIG2#4 w10: J1.16@190,2200 142.8,2247.2 142.8,2957.08 345,3159.28 J14.2@345,3255
NetL1_1: L1.1 U8.1 U8.2 U8.3
NetL2_1: L2.1 U9.A2 U9.B2 U9.C2 | length 257.9
  TOP LAYER w15: U9.C2@1404.84,1929.84 U9.B2@1424.52,1929.84 U9.A2@1444.21,1929.84
  TOP LAYER w17: U9.A2@1444.21,1929.84 1462.75,1929.84 1467.71,1934.8 1658.3,1934.8 L2.1@1660,1936.5
NetL3_1: L3.1 U9.D2 U9.E2 U9.F2 | length 251.5
  TOP LAYER w15: U9.F2@1345.78,1929.84 U9.E2@1365.47,1929.84 U9.D2@1385.15,1929.84
  TOP LAYER w17: L3.1@1135,1926.5 1138.35,1929.84 U9.F2@1345.78,1929.84
NetL4_1: L4.1 U10.A2 U10.B2 U10.C2 | length 280.9
  TOP LAYER w15: U10.C2@2525,1459.68 U10.B2@2525,1479.37 U10.A2@2525,1499.06
  TOP LAYER w17: L4.1@2523.5,1740 2525,1738.5 U10.A2@2525,1499.06
NetL5_1: L5.1 U10.D2 U10.E2 U10.F2 | length 256.4
  TOP LAYER w15: U10.F2@2525,1400.63 U10.E2@2525,1420.31 U10.D2@2525,1440
  TOP LAYER w17: U10.F2@2525,1400.63 2525,1188.5 L5.1@2528.5,1185
NetL6_1: L6.1 U11.1 U11.2 U11.3
NetR3_2: R3.2 U12.1 | length 1248.3
  SIG2#4 w30: v1(1270,3100) 1377.18,2992.82 1484.87,2992.82 1512.11,2965.58 1780.19,2965.58 1831.47,2914.3 1831.47,2453.19 v1(1878.31,2406.35)
  BOTTOM LAYER w20: U12.1@1878,2364.5 1878,2406.04 v1(1878.31,2406.35)
  BOTTOM LAYER w30: R3.2@1230,3098.5 1268.5,3098.5 v1(1270,3100)
NetR4_2: R4.2 U13.1 | length 870.9
  SIG2#4 w30: v1(1373.26,3100.9) 1424.55,3049.61 1519.55,3049.61 1549.16,3020 2006.46,3020 v1(2099.68,2926.78)
  BOTTOM LAYER w10: U13.1@2064.5,2927 2099.46,2927 v1(2099.68,2926.78)
  BOTTOM LAYER w30: v1(1373.26,3100.9) 1374.16,3100 R4.2@1410,3100
NetR5_2: R5.2 U14.1 | length 319.1
  SIG2#4 w30: v1(2462.63,2903.32) 2487.27,2903.32 2511.77,2927.82 2511.77,3047.97 v1(2471.02,3088.72)
  BOTTOM LAYER w20: v1(2462.63,2903.32) 2462.95,2903 U14.1@2500.5,2903
  BOTTOM LAYER w30: v1(2471.02,3088.72) 2471.24,3088.5 R5.2@2515,3088.5
NetR6_2: R6.2 U15.1 | length 1258.3
  SIG2#4 w25: v1(2273,2197) 2340.89,2197 2368.25,2224.36 2368.25,2339.49 2413.63,2384.87 2540.47,2384.87 2624.4,2468.8 2624.4,2835.9 2594.22,2866.08 2594.22,3037.22 v1(2646,3089)
  BOTTOM LAYER w25: v1(2273,2197) U15.1@2309.5,2197 ; v1(2646,3089) 2645.5,3089 2645,3088.5 R6.2@2680,3088.5
NetR7_2: R7.2 U16.1 | length 2141.5
  SIG2#4 w30: v1(2713,2390) 2699.96,2403.04 2699.96,2694.37 2764,2758.41 2764,3013.48 2786.32,3035.8 2786.32,3399.37 2991.95,3605 3240,3605 3277.5,3567.5 3277.5,3457.5 3320,3415 v1(3570,3415)
  BOTTOM LAYER w25: U16.1@2713,2349.5 v1(2713,2390) ; v1(3570,3415) R7.2@3608.5,3415
NetR8_2: R8.2 U17.1 | length 184.1
  SIG2#4 w25: v1(2821,2957) 2855,2991 v1(2855,3050)
  BOTTOM LAYER w25: v1(2821,2957) U17.1@2859.5,2957 ; v1(2855,3050) R8.2@2855,3088.5
NetR9_2: R9.2 U18.1 | length 303.8
  SIG2#4 w25: v1(3168,3083) 3168,2937.3 3212.3,2893 v1(3231,2893)
  BOTTOM LAYER w25: v1(3168,3083) 3168.5,3083.5 R9.2@3205,3083.5 ; v1(3231,2893) U18.1@3270.5,2893
NetR10_2: R10.2 U19.1 | length 1124.7
  SIG2#4 w25: v1(2998.26,3084.41) 3071.78,3010.89 3071.78,2970.02 3288.67,2753.13 3288.67,2357.33 3349,2297 3349,2245 3326.75,2222.75 v1(3295.75,2222.75)
  BOTTOM LAYER w10: v1(2998.26,3084.41) v1@2998.34,3084.49
  BOTTOM LAYER w25: v1@2998.34,3084.49 2999.32,3083.5 R10.2@3035,3083.5 ; U19.1@3255.5,2223 3255.75,2222.75 v1(3295.75,2222.75)
NetR11_2: R11.2 U20.1 | length 1003
  SIG2#4 w30: v1(1215.54,1368.43) 1400.14,1183.83 v1(1400.14,508.53)
  BOTTOM LAYER w10: v1@1215.5,1368.47 v1(1215.54,1368.43)
  BOTTOM LAYER w25: v1@1215.5,1368.47 U20.1@1215.5,1398
  BOTTOM LAYER w30: R11.2@1400,471.5 1400,508.39 v1(1400.14,508.53)
NetR12_2: R12.2 U21.1 | length 1380.9
  SIG2#4 w25: v1(484.15,1424.19) 300.48,1240.52 300.48,945.66 436.81,809.33 436.81,596.54 499.68,533.67 730,533.67 v1(755.14,508.53)
  BOTTOM LAYER w25: v1(484.15,1424.19) 512.69,1424.19 U21.1@513,1424.5 ; R12.2@755,471.5 v1@755,508.39
NetR13_2: R13.2 U22.1 | length 906.5
  SIG2#4 w30: v1(388.67,1265.45) 587.29,1464.07 587.29,1848.44 633.23,1894.38 633.23,1955.39 v1(607.08,1981.54)
  BOTTOM LAYER w6: v1@606.62,1982 v1(607.08,1981.54)
  BOTTOM LAYER w10: v1@388.5,1265.28 v1(388.67,1265.45)
  BOTTOM LAYER w25: R13.2@388.5,1225 v1@388.5,1265.28 ; U22.1@569.5,1982 v1@606.62,1982
NetR14_2: R14.2 U23.1 | length 3423.4
  SIG2#4 w30: v1(1075.94,516.95) 1121.68,471.21 1121.68,360.57 1087.78,326.67 558.94,326.67 352.2,533.41 352.2,832.85 252.57,932.48 252.57,1259.45 506.43,1513.31 506.43,1848.44 557.56,1899.57 557.56,2008.58 594.36,2045.38 1192.23,2045.38 v1(1202.58,2035.03)
  BOTTOM LAYER w10: v1@1202.11,2035.5 v1(1202.58,2035.03)
  BOTTOM LAYER w25: U23.1@1177,2035.5 v1@1202.11,2035.5
  BOTTOM LAYER w30: R14.2@1075,471.5 1075,516.01 v1(1075.94,516.95)
NetR15_2: R15.2 U24.1 | length 1068.8
  SIG2#4 w30: v1(2277.39,1480.62) 2325.14,1432.87 v1(2325.14,509.51)
  BOTTOM LAYER w20: U24.1@2277,1520.5 2277,1481.01 v1(2277.39,1480.62)
  BOTTOM LAYER w30: R15.2@2325,471.5 v1@2325,509.37
NetR16_2: R16.2 U25.1 | length 1164.6
  SIG2#4 w30: v1(1473.9,1469.5) 1433,1428.6 1433,1255.94 1508.79,1180.15 1508.79,700.21 v1(1700,509)
  BOTTOM LAYER w25: v1(1473.9,1469.5) U25.1@1513,1469.5
  BOTTOM LAYER w30: R16.2@1700,471.5 v1(1700,509)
